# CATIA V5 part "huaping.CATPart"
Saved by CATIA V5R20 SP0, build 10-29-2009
Part number: 花瓶
Material "Bordeaux Red": density 7860 kg/m3, Young's modulus 2e+11 Pa, Poisson ratio 0.266
Material "DS Gold": density 7860 kg/m3, Young's modulus 2e+11 Pa, Poisson ratio 0.266
Material "Multicoloured Flag"
Bounding box of the stored display mesh (mm): x -46.554 to 34.061, y -34.045 to 34.01, z -0.166 to 79.03
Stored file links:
  G:\huaping.CATPart
  D:\CATIA VR20\win_b64\startup\materials\Catalog.CATMaterial
  D:\CATIA VR20\win_b64\startup\materials\honeycomb.jpg
  D:\CATIA VR20\win_b64\startup\materials\DS_star.jpg
  D:\CATIA VR20\win_b64\startup\materials\yellow_env_512x512.jpg
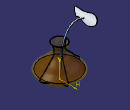
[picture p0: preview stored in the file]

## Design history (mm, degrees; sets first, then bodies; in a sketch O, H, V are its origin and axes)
Body1 (main body), material "DS Gold"
  Plane1: type Offset, RefPlane xy-plane, Offset 15
  Plane2: type Offset, RefPlane Plane1, Offset 9
  Plane3: type Offset, RefPlane Plane2, Offset 20
  Plane4: type Offset, RefPlane Plane3, Offset 11
  Sketch1 on xy-plane, origin (0, 0, 0), H (1, 0, 0), V (0, 1, 0)
    circle A1 centre (0, 0) radius 10
  Sketch2 on Plane1, origin (0, 0, 15), H (1, 0, 0), V (0, 1, 0)
    circle A1 centre (0, 0) radius 34.0606
  Sketch3 on Plane2, origin (0, 0, 24), H (1, 0, 0), V (0, 1, 0)
    circle A1 centre (0, 0) radius 25.1206
  Sketch4 on Plane3, origin (0, 0, 44), H (1, 0, 0), V (0, 1, 0)
    circle A1 centre (0, 0) radius 9.9467
  Sketch5 on Plane4, origin (0, 0, 55), H (1, 0, 0), V (0, 1, 0)
    circle A1 centre (0, 0) radius 12.0139
  Loft1: solid, Sections (Sketch1; Sketch2; Sketch3; Sketch4; Sketch5)
  Shell1: IntOffset 1, Face face of Loft1, ExtOffset 0
  Sketch6 on yz-plane, origin (0, 0, 0), H (0, 1, 0), V (0, 0, 1)
Body2, material "Multicoloured Flag"
  Sketch7 on zx-plane, origin (0, 0, 0), H (-1, 0, 0), V (0, 0, 1)
    spline S1 through (3.3521, 0) (2.4496, 34.6996) (21.7885, 71.3313) (42.0298, 69.0178)
    point P1 (3.3521, 0)
    coincidence: P1 H
  Plane5: type Normal, Curve Sketch7, RefPoint vertex of Sketch7
  Sketch8 on Plane5, origin (-7.7283, 0, -3.6481), H (0, 1, 0), V (-0.4269, 0, 0.9043)
    spline S1 through (-11.9026, 77.0612) (-17.9079, 87.782) (1.9234, 88.4781) (16.0288, 90.1489) (21.0564, 84.3012) (5.5545, 74.4158) (-6.037, 78.3143) (-11.9026, 77.0612)
    point P1 (-11.9026, 77.0612)
    point P2 (-11.9026, 77.0612)
    coincidence: P1 P2
  Pad1: profile Sketch8, direction (0.9043, 0, 0.4269), length 1
  Sketch9 on Plane5, origin (-7.7283, 0, -3.6481), H (0, 1, 0), V (-0.4269, 0, 0.9043)
    circle A1 centre (0, 80) radius 1
    point P1 (0, 80)
    radius A1 = 1
    coincidence: P1 V
  Rib1: profile Sketch9, centre curve Sketch7
Body3, material "Bordeaux Red"
  Sketch10 on zx-plane, origin (0, 0, 0), H (-1, 0, 0), V (0, 0, 1)
    axis line L1 (0, 72.4224) -> (0, -20.0672)
    point P1 (0, 72.4224)
    line L2 (0, 15.1062) -> (31.1387, 15.1062)
    point P3 (0, 15.1062)
    arc A1 centre (2.67, 38.2759) radius 36.7056 from (31.1387, 15.1062) to (0, 1.6675) cw
    point P6 (0, 1.6675)
    coincidence: P1 V, P3 L1, P6 L1
    vertical: L1 V
    horizontal: L2 H
  Shaft1: profile Sketch10, axis Sketch10.L1, angle 360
